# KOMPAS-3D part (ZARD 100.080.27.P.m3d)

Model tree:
1. Операция без истории:1
2. Операция без истории:2
3. Операция без истории:3
4. Операция без истории:4
5. Операция без истории:5
6. Операция без истории:6
7. Операция без истории:7
8. Операция без истории:8
9. Операция без истории:9
10. Операция без истории:10
11. Операция без истории:11
12. Операция без истории:12
13. Операция без истории:13
14. Операция без истории:14
15. Операция без истории:15
16. Операция без истории:16
17. Операция без истории:17
18. Операция без истории:18
19. Операция без истории:19
20. Операция без истории:20
21. Операция без истории:21
22. Операция без истории:22
23. Операция без истории:23
24. Операция без истории:24
25. Операция без истории:25
26. Операция без истории:26
27. Операция без истории:27
28. Операция без истории:28
29. Операция без истории:29
30. Операция без истории:30
31. Операция без истории:31
32. Операция без истории:32
33. Операция без истории:33
34. Операция без истории:34
35. Операция без истории:35
36. Операция без истории:36
37. Операция без истории:37
38. Операция без истории:38
39. Операция без истории:39
40. Операция без истории:40
41. Операция без истории:41
42. Операция без истории:42
43. Операция без истории:43
44. Операция без истории:44
45. Операция без истории:45
46. Операция без истории:46
47. Операция без истории:47
48. Операция без истории:48
49. Операция без истории:49
50. Операция без истории:50
51. Операция без истории:51
52. Операция без истории:52
53. Операция без истории:53
54. Операция без истории:54
55. Операция без истории:55
56. Операция без истории:56
57. Операция без истории:57
58. Операция без истории:58
59. Операция без истории:59
60. Операция без истории:60
61. Операция без истории:61
62. Операция без истории:62
63. Операция без истории:63
64. Операция без истории:64
65. Операция без истории:65
66. Операция без истории:66
67. Операция без истории:67
68. Операция без истории:68
69. Операция без истории:69
70. Операция без истории:70
71. Операция без истории:71
72. Операция без истории:72
73. Операция без истории:73
74. Операция без истории:74
75. Операция без истории:75
76. Операция без истории:76
77. Операция без истории:77
78. Операция без истории:78
79. Операция без истории:79
80. Операция без истории:80
81. Операция без истории:81
82. Операция без истории:82
83. Операция без истории:83
84. Операция без истории:84
85. Операция без истории:85
86. Операция без истории:86
87. Операция без истории:87
88. Поверхность без истории:1
89. Поверхность без истории:2
90. Поверхность без истории:3
91. Поверхность без истории:4
92. Поверхность без истории:5
93. Поверхность без истории:6
94. Поверхность без истории:7
95. Поверхность без истории:8

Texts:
  ЗАРД 100.080.27-ХХ.Р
